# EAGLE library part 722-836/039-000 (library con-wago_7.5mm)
Serie 722, Federleiste mit Verriegelungsklinken / Series 722, Female connector with locking levers Polzahl / Pole No.: 6 Rastermaß / Pitch: 7.5 mm Bemessungsspannung / Rated Voltage: 630 V Nennstrom / Nominal Current: 12 A Lötstiftlänge: / Solder Pin Length: 5 mm Farbe / Color: lichtgrau / light gray Stand: 01.01.2012. Die jeweils aktuellen Daten zu diesem Artikel finden Sie in unserem Produktkatalog, den Sie unter www.wago.com einsehen können. As of: 01/01/2012. Please find the newest data for this article in our product catalogue, which can be viewed under www.wago.com.
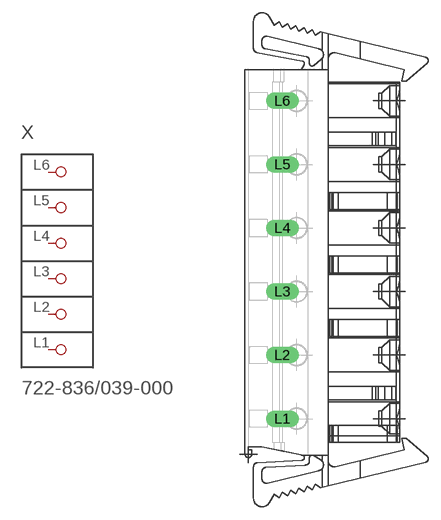
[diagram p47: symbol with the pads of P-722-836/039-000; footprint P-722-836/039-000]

Designator prefix X

## 722-836/039-000  [P-722-836/039-000]
L1  P1
L2  P2
L3  P3
L4  P4
L5  P5
L6  P6

## Footprint P-722-836/039-000 (pad centres in mm)
drill 1.3 long: L1 -6.089,-18.75; L2 -6.089,-11.25; L3 -6.089,-3.75; L4 -6.089,3.75; L5 -6.089,11.25; L6 -6.089,18.75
